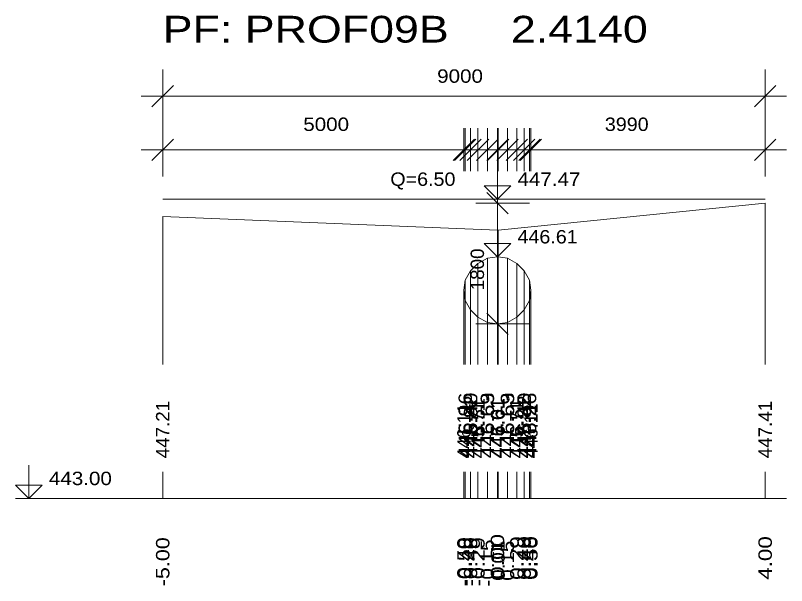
# Model space of a CAD drawing. Extents: x 7 to 442, y -393 to 441.
# Drawn here: x 294.44 to 305.95, y -130.1 to -121.58 of the extents above; entities that cross this region are included whole.
import ezdxf

# ---------------------------------------------------------------- set-up
doc = ezdxf.new("R2010")
doc.units = 0
doc.header["$LTSCALE"] = 0.08
doc.layers.add('7', color=7, linetype='Continuous', lineweight=13)

msp = doc.modelspace()

# ---------------------------------------------------------------- linework, layer by layer
at = {"layer": '7'}
for p, q in [((296.635, -123.99), (296.635, -122.39)), ((305.635, -123.99), (305.635, -122.39)), ((296.475, -122.95), (296.795, -122.63)), ((305.475, -122.95), (305.795, -122.63)), ((296.315, -122.79), (305.955, -122.79)), ((296.635, -123.91), (296.635, -123.27)), ((301.135, -123.91), (301.135, -123.27)), ((301.155, -123.91), (301.155, -123.27)), ((301.155, -123.91), (301.155, -123.27)), ((301.235, -123.91), (301.235, -123.27)), ((301.235, -123.91), (301.235, -123.27)), ((301.345, -123.91), (301.345, -123.27)), ((301.345, -123.91), (301.345, -123.27)), ((301.485, -123.91), (301.485, -123.27)), ((301.485, -123.91), (301.485, -123.27)), ((301.635, -123.91), (301.635, -123.27)), ((301.635, -123.91), (301.635, -123.27)), ((301.635, -123.91), (301.635, -123.27)), ((301.645, -123.91), (301.645, -123.27)), ((301.645, -123.91), (301.645, -123.27)), ((301.785, -123.91), (301.785, -123.27)), ((301.785, -123.91), (301.785, -123.27)), ((301.925, -123.91), (301.925, -123.27)), ((301.925, -123.91), (301.925, -123.27)), ((302.035, -123.91), (302.035, -123.27)), ((302.035, -123.91), (302.035, -123.27)), ((302.115, -123.91), (302.115, -123.27)), ((302.115, -123.91), (302.115, -123.27)), ((302.135, -123.91), (302.135, -123.27)), ((305.635, -123.91), (305.635, -123.27)), ((296.475, -123.75), (296.795, -123.43)), ((300.975, -123.75), (301.295, -123.43)), ((300.995, -123.75), (301.315, -123.43)), ((300.995, -123.75), (301.315, -123.43)), ((301.075, -123.75), (301.395, -123.43)), ((301.075, -123.75), (301.395, -123.43)), ((301.185, -123.75), (301.505, -123.43)), ((301.185, -123.75), (301.505, -123.43)), ((301.325, -123.75), (301.645, -123.43)), ((301.325, -123.75), (301.645, -123.43)), ((301.475, -123.75), (301.795, -123.43)), ((301.475, -123.75), (301.795, -123.43)), ((301.475, -123.75), (301.795, -123.43)), ((301.485, -123.75), (301.805, -123.43)), ((301.485, -123.75), (301.805, -123.43)), ((301.625, -123.75), (301.945, -123.43)), ((301.625, -123.75), (301.945, -123.43)), ((301.765, -123.75), (302.085, -123.43)), ((301.765, -123.75), (302.085, -123.43)), ((301.875, -123.75), (302.195, -123.43)), ((301.875, -123.75), (302.195, -123.43)), ((301.955, -123.75), (302.275, -123.43)), ((301.955, -123.75), (302.275, -123.43)), ((301.975, -123.75), (302.295, -123.43)), ((305.475, -123.75), (305.795, -123.43)), ((296.315, -123.59), (305.955, -123.59)), ((301.635, -126.35), (301.635, -124.07)), ((301.795, -124.55), (301.475, -124.23)), ((296.635, -124.33), (305.635, -124.33)), ((301.315, -124.39), (302.115, -124.39)), ((305.635, -126.8), (305.635, -124.39)), ((296.635, -126.8), (296.635, -124.59)), ((301.635, -126.8), (301.635, -124.79)), ((301.645, -126.8), (301.645, -124.79)), ((301.485, -126.8), (301.485, -125.21)), ((301.635, -126.8), (301.635, -125.19)), ((301.635, -125.19), (301.645, -125.19)), ((301.645, -126.8), (301.645, -125.19)), ((301.785, -126.8), (301.785, -125.21)), ((301.345, -126.8), (301.345, -125.29)), ((301.925, -126.8), (301.925, -125.29)), ((301.235, -126.8), (301.235, -125.4)), ((302.035, -126.8), (302.035, -125.4)), ((301.155, -126.8), (301.155, -125.54)), ((302.115, -126.8), (302.115, -125.54)), ((301.135, -126.8), (301.135, -125.69)), ((302.135, -126.8), (302.135, -125.69)), ((301.155, -126.8), (301.155, -125.84)), ((302.115, -126.8), (302.115, -125.84)), ((301.235, -126.8), (301.235, -125.98)), ((302.035, -126.8), (302.035, -125.98)), ((301.345, -126.8), (301.345, -126.09)), ((301.795, -126.35), (301.475, -126.03)), ((301.925, -126.8), (301.925, -126.09)), ((301.315, -126.19), (302.115, -126.19)), ((301.485, -126.8), (301.485, -126.17)), ((301.635, -126.8), (301.635, -126.19)), ((301.785, -126.8), (301.785, -126.17)), ((296.635, -128.8), (296.635, -128.4)), ((301.135, -128.8), (301.135, -128.4)), ((301.155, -128.8), (301.155, -128.4)), ((301.155, -128.8), (301.155, -128.4)), ((301.235, -128.8), (301.235, -128.4)), ((301.235, -128.8), (301.235, -128.4)), ((301.345, -128.8), (301.345, -128.4)), ((301.345, -128.8), (301.345, -128.4)), ((301.485, -128.8), (301.485, -128.4)), ((301.485, -128.8), (301.485, -128.4)), ((301.635, -128.8), (301.635, -128.4)), ((301.635, -128.8), (301.635, -128.4)), ((301.635, -128.8), (301.635, -128.4)), ((301.645, -128.8), (301.645, -128.4)), ((301.645, -128.8), (301.645, -128.4)), ((301.785, -128.8), (301.785, -128.4)), ((301.785, -128.8), (301.785, -128.4)), ((301.925, -128.8), (301.925, -128.4)), ((301.925, -128.8), (301.925, -128.4)), ((302.035, -128.8), (302.035, -128.4)), ((302.035, -128.8), (302.035, -128.4)), ((302.115, -128.8), (302.115, -128.4)), ((302.115, -128.8), (302.115, -128.4)), ((302.135, -128.8), (302.135, -128.4)), ((305.635, -128.8), (305.635, -128.4)), ((294.435, -128.8), (305.955, -128.8))]:
    msp.add_line(p, q, dxfattribs=at)
for points in [[(301.635, -123.83), (301.635, -124.33), (301.435, -124.13), (301.835, -124.13), (301.635, -124.33)], [(296.635, -124.59), (301.635, -124.79), (301.635, -125.19), (301.485, -125.21), (301.345, -125.29), (301.235, -125.4), (301.155, -125.54), (301.135, -125.69), (301.155, -125.84), (301.235, -125.98), (301.345, -126.09), (301.485, -126.17), (301.635, -126.19), (301.785, -126.17), (301.925, -126.09), (302.035, -125.98), (302.115, -125.84), (302.135, -125.69), (302.115, -125.54), (302.035, -125.4), (301.925, -125.29), (301.785, -125.21), (301.645, -125.19), (301.645, -124.79), (305.635, -124.39)], [(301.635, -124.69), (301.635, -125.19), (301.435, -124.99), (301.835, -124.99), (301.635, -125.19)], [(294.635, -128.3), (294.635, -128.8), (294.435, -128.6), (294.835, -128.6), (294.635, -128.8)]]:
    msp.add_lwpolyline(points, dxfattribs=at)

# ---------------------------------------------------------------- texts
for s, height, width, p in [('PF: PROF09B     2.4140', 0.4, 1.25, (296.635, -121.99)), ('9000', 0.2, 1.15, (300.735, -122.59)), ('5000', 0.2, 1.15, (298.735, -123.31)), ('3990', 0.2, 1.1, (303.24, -123.31)), ('Q=6.50', 0.2, 1.1, (300.035, -124.13)), ('447.47', 0.2, 1.15, (301.935, -124.13)), ('446.61', 0.2, 1.1, (301.935, -124.99)), ('443.00', 0.2, 1.15, (294.935, -128.6))]:
    msp.add_text(s, height=height, dxfattribs=dict(at, width=width)).set_placement(p)
for s, width, p in [('1800', 1.05, (301.435, -125.69)), ('446.26 ', 1.2, (301.255, -128.2)), ('445.96 ', 1.2, (301.255, -128.2)), ('446.40 ', 1.2, (301.335, -128.2)), ('445.82 ', 1.15, (301.335, -128.2)), ('445.63 ', 1.2, (301.585, -128.2)), ('446.59 ', 1.2, (301.585, -128.2)), ('445.63 ', 1.2, (301.885, -128.2)), ('446.59 ', 1.2, (301.885, -128.2)), ('446.40 ', 1.2, (302.135, -128.2)), ('445.82 ', 1.15, (302.135, -128.2)), ('445.96 ', 1.2, (302.215, -128.2)), ('446.26 ', 1.2, (302.215, -128.2)), ('447.21 ', 1.05, (296.735, -128.2)), ('446.51 ', 1.1, (301.445, -128.2)), ('445.71 ', 1.05, (301.445, -128.2)), ('447.01 ', 1.1, (301.735, -128.2)), ('446.61 ', 1.1, (301.735, -128.2)), ('445.61 ', 1.1, (301.735, -128.2)), ('446.61 ', 1.1, (301.745, -128.2)), ('447.01 ', 1.1, (301.745, -128.2)), ('446.51 ', 1.1, (302.025, -128.2)), ('445.71 ', 1.05, (302.025, -128.2)), ('447.41 ', 1.05, (305.735, -128.2)), ('  0.00 ', 1.3, (301.735, -130.2)), ('  0.00 ', 1.3, (301.735, -130.2)), ('  0.00 ', 1.3, (301.735, -130.2)), (' -5.00 ', 1.2, (296.735, -130.2)), (' -0.50 ', 1.2, (301.235, -130.2)), (' -0.48 ', 1.2, (301.255, -130.2)), (' -0.48 ', 1.2, (301.255, -130.2)), (' -0.40 ', 1.2, (301.335, -130.2)), (' -0.40 ', 1.2, (301.335, -130.2)), (' -0.29 ', 1.2, (301.445, -130.2)), (' -0.29 ', 1.2, (301.445, -130.2)), (' -0.15 ', 1.15, (301.585, -130.2)), (' -0.15 ', 1.15, (301.585, -130.2)), ('  0.01 ', 1.15, (301.745, -130.2)), ('  0.01 ', 1.15, (301.745, -130.2)), ('  0.15 ', 1.15, (301.885, -130.2)), ('  0.15 ', 1.15, (301.885, -130.2)), ('  0.29 ', 1.25, (302.025, -130.2)), ('  0.29 ', 1.25, (302.025, -130.2)), ('  0.40 ', 1.25, (302.135, -130.2)), ('  0.40 ', 1.25, (302.135, -130.2)), ('  0.48 ', 1.25, (302.215, -130.2)), ('  0.48 ', 1.25, (302.215, -130.2)), ('  0.50 ', 1.25, (302.235, -130.2)), ('  4.00 ', 1.25, (305.735, -130.2))]:
    msp.add_text(s, height=0.2, rotation=90, dxfattribs=dict(at, width=width)).set_placement(p)
for p in [(301.235, -128.2), (302.235, -128.2)]:
    msp.add_text('446.11 ', height=0.2, rotation=90, dxfattribs=at).set_placement(p)

doc.saveas('drawing.dxf')
